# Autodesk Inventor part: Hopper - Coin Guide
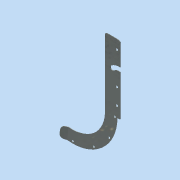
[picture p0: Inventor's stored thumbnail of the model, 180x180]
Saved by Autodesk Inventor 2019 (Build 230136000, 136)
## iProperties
Created: 2005-11
Part Number: Hopper - Coin Guide
Document SubType Name: Sheet Metal
Designer: floress
Material: Steel, Mild
Density: 7.85 g/cm^3
Sheet Metal Rule: Default
Appearance: Zinc
Flat Pattern Width: 9.20466 cm
Flat Pattern Length: 17.6733 cm
Flat Pattern Area: 162.676 cm^2
Sheet Metal Width: 3.624 in
Sheet Metal Length: 6.958 in
Sheet Metal Area: 25.215 in^2
Author: floress
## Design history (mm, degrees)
node "Face1"
  sketch "Sketch1"
    geometry: L1 (42.879, 91.251)-(60.454, 91.251); L2 (39.704, -12.664)-(39.704, 88.076); L3 (59.398, -15.798)-(62.677, -15.798); L4 (-17.576, -66.42)-(-19.993, -84.894); L5 (63.629, 88.076)-(63.629, 55.375); L6 (63.629, 48.995)-(63.629, -14.845); C1 r 1.524 at (-10.983, -82.092); C2 r 1.524 at (22.038, -73.244); C3 r 1.524 at (46.211, -49.071); C4 r 1.524 at (55.059, -16.05); C5 r 1.778 at (58.303, 0.763); C6 r 1.778 at (58.303, 26.163); C7 r 1.778 at (58.303, 76.963); A1 r 50.8 centre (-10.983, -16.05) between (-17.576, -66.42) and (39.704, -12.664); A2 r 0.953 centre (59.398, -16.75) between (59.398, -15.798) and (58.445, -16.741); A3 r 0.953 centre (62.677, -14.845) between (62.677, -15.798) and (63.629, -14.845); A4 r 69.432 centre (-10.983, -16.05) between (-19.993, -84.894) and (58.445, -16.741); A5 r 3.175 centre (60.454, 88.076) between (63.629, 88.076) and (60.454, 91.251); A6 r 3.175 centre (42.879, 88.076) between (42.879, 91.251) and (39.704, 88.076); A7 r 3.175 centre (51.39, 48.388) between (49.35, 50.821) and (53.43, 45.956); A8 r 19.75 centre (62.042, 35.688) between (63.629, 55.375) and (49.35, 50.821); A9 r 13.4 centre (62.042, 35.688) between (63.629, 48.995) and (53.43, 45.956)
    constraints: 18 point on circle, 16 centre point, 12 end point, 10 tangent, 6 equal radius, 2 coincident, 2 parallel, 2 perpendicular, 1 horizontal
    dimensions: "d4" = 101.6 diameter of A1; "d5" = 1.905 diameter of A2; "d8" = 3.556 diameter of C7; "d9" = 3.048 diameter of C2; "d10" = 3.175 radius of A5
node "Flange1"
feature "Corner Round1" dims "d18" = 6.35
body "Solid1"
face "Plate1" dims "d19" = 0.79375 (= Thickness)
sketch "Sketch2"
  geometry: L1 through (9.316, 0) direction (1, -1.49e-17); L2 (18.632, 0)-(18.632, 9.525); L3 (18.632, 9.525)-(0, 9.525); L4 through (0, 4.763) direction (7.28e-16, -1)
  constraints: 6 end point, 1 horizontal, 1 perpendicular, 1 vertical
face "Plate2" dims "d11" = 0.79375 (= BendReliefWidth), "d13" = 1.5875 (= MinimumRemnant), "d15" = 9.525, "d16" = -30 deg, "d17" = 0.79375 (= BendRadius), "d19" = 0.79375 (= Thickness)
bend "Bend1" dims "d11" = 0.79375 (= BendReliefWidth), "d12" = 0.39687 (= BendReliefDepth), "d13" = 1.5875 (= MinimumRemnant), "d14" = 0.79375 (= BendRadius), "d15" = 9.525, "d16" = -30 deg, "d17" = 0.79375 (= BendRadius), "d19" = 0.79375 (= Thickness), "SeamGap" = 0.00508
feature "Definition1"
other parameters: "Thickness" = 0.79375, "BendRadius" = 0.79375 (= Thickness), "BendReliefWidth" = 0.79375 (= Thickness), "BendReliefDepth" = 0.39687 (= 0.5 x Thickness), "CornerReliefSize" = 3.175 (= 4 x Thickness), "MinimumRemnant" = 1.5875 (= 2 x Thickness), "TransitionRadius" = 0.79375 (= BendRadius), "d0" = 0.79375 (= BendRadius), "d1" = 0.39687, "JacobiRadiusSize" = 0.79375 (= Thickness), "GapSize" = 0.79375 (= Thickness), "BendRadius" = 0.79375, "BendReliefDepth" = 0.39687, "BendReliefWidth" = 0.79375, "CornerReliefSize" = 3.175, "GapSize" = 0.79375, "JacobiRadiusSize" = 0.79375, "MinimumRemnant" = 1.5875, "Thickness" = 0.79375, "TransitionRadius" = 0.79375
